(* Logix 5000 project; controller SmartVs_V02 1769-L33ERM rev 32.11; software revision 32.01; part 2 of 2 *)
(* tags used below, declared in another part *)
   UDP_Data : SKT_DATA_UDP;   // Holds all data sent and recieved by message instructions
   Enable_Socket : BOOL;   // Set by user to enable or disable socket
   ENABLED : BOOL;
   OPEN : BOOL;   // The Socket is Open
   READ : BOOL;   // New data in read buffer.
   WRITE : BOOL;   // Set bit to write data.
   ERROR : BOOL;   // Set if any message has an error.
   State : DINT;   // Current state
(* SKT_AOI_UDP, continued *)

ROUTINE Prescan   (* ladder *)
// Prescan
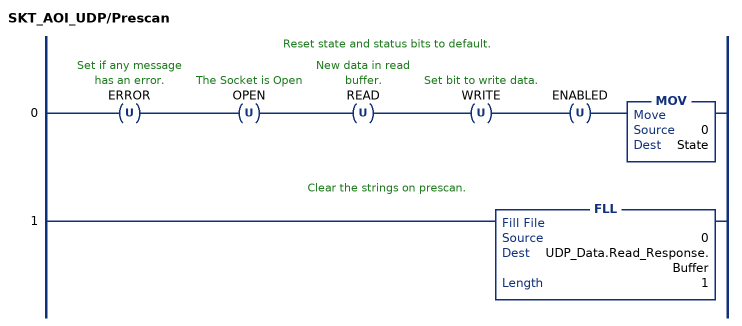
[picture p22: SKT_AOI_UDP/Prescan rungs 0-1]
   // Reset state and status bits to default.
   0: OTU(ERROR)OTU(OPEN)OTU(READ)OTU(WRITE)OTU(ENABLED)MOV(0,State);
   // Clear the strings on prescan.
   1: FLL(0,UDP_Data.Read_Response.Buffer,1);
END_ROUTINE
END_ADD_ON_INSTRUCTION

ADD_ON_INSTRUCTION SmartVS   (* revision 1.0 *)
VAR_INPUT
   i_xEnable : BOOL;
   i_xWrite : BOOL;
   i_xReset : BOOL;
   i_iJobData : INT;
END_VAR
VAR_OUTPUT
   o_xEnabled : BOOL; {access Read Only}
   o_xError : BOOL; {access Read Only}
END_VAR
VAR_IN_OUT
   o_sStringResult : STRING; {required}
END_VAR
VAR_OUTPUT
   o_iErrorCode : INT; {access Read Only}
END_VAR
VAR_INPUT
   i_iIPaddr1 : INT;
   i_iIPaddr2 : INT;
   i_iIPaddr3 : INT;
   i_iIPaddr4 : INT;
END_VAR
VAR_IN_OUT
   MSG_Client_Connect : MESSAGE; {required}
   DATA_Client : SKT_DATA_CLIENT; {required}
   MSG_Client_Create : MESSAGE; {required}
   MSG_Client_Delete : MESSAGE; {required}
   MSG_Client_Read : MESSAGE; {required}
   MSG_Client_Write : MESSAGE; {required}
   MSG_Delete_All : MESSAGE; {required}
END_VAR
VAR_OUTPUT
   o_diExtErrorCode : DINT; {access Read Only}
END_VAR
VAR
   Client_Buffer : STR_480;
   iErrorCode : INT; {access None}
   iErrorState : INT; {access None}
   Write_Data_Client : BOOL;
   Write_Data_Server : BOOL;
   Write_Data_UDP : BOOL;
   ifindDONE : INT; {access None}
   ifindFAIL : INT; {access None}
   iOldJobData : INT := -1; {access None}
   iOldIPaddr1 : INT := -1; {access None}
   sJobDone : STRING := 'Job DONE';
   sJobFailed : STRING := 'Job FAIL';
   sJobLoadString : STRING := 'job load ';
   String_1 : STRING;
   sRLString : STRING := '$0D$0A';
   String_3 : STRING;
   String_4 : STRING;
   xBitTrig : FBD_ONESHOT := (InputBit := 1);
   xDeleteMsg : BOOL;
   iOldIPaddr2 : INT := -1; {access None}
   iOldIPaddr3 : INT := -1; {access None}
   sJobData : STRING; {access None}
   diString_1Len : DINT; {access None}
   sDONE : STRING := 'DONE'; {access None}
   sFAIL : STRING := 'FAIL'; {access None}
   sResponseError : STRING := 'Response Error'; {access None}
   sErrorState : STRING := 'Error State'; {access None}
   sIPaddr1 : STRING; {access None}
   sIPaddr2 : STRING; {access None}
   sIPaddr3 : STRING; {access None}
   sIPaddr4 : STRING; {access None}
   sDot : STRING := '.'; {access None}
   sDotIPaddr4 : STRING; {access None}
   sDotIPaddr2 : STRING; {access None}
   sDotIPaddr3 : STRING; {access None}
   sIPaddrComplete : STRING; {access None}
   sPortNumber : STRING := '?port=23'; {access None}
   sEmpty : STRING; {access None}
   ReadTimer : FBD_TIMER; {access None}
   iOldIPaddr4 : INT := -1; {access None}
   iQuantity : INT; {access None}
   iStartCopy : INT; {access None}
   iState : INT; {access None}
   sLRRL : STRING := '$0A$0D$0D$0A'; {access None}
   iFailInfoEnd : DINT; {access None}
   sJobFailedInfo : STRING; {access None}
   sJobFailedCompleted : STRING; {access None}
   iExtErrorCode : DINT; {access None}
   TCP_Client : SKT_AOI_TCP_CLIENT; {access None}
   StringResetTimer : FBD_TIMER; {access None}
   sSmartVSanswer : STRING; {access None}
   String_5 : STRING; {access None}
   sSearchDONE : STRING; {access None}
   sSearchFAIL : STRING; {access None}
   ifindFAIL_1 : INT;
   SmartVS_DB : INT; {access None}
   sSpace : STRING := ' '; {access None}
   String_2 : STRING; {access None}
END_VAR

ROUTINE Logic   (* structured text *)
   
   //AOI used for TCP/IP communication with Datalogic SmartVS in order to perform "job change" opearation
   //Author: Lorenzo Draghetti
   
   
   //Delete all sockets at start and reset
   if S:FS OR xDeleteMsg then
   	MSG(MSG_Delete_All);
   	xDeleteMsg := 0;
   end_if;
   
   //Set time to wait before to read SmartVS' answer
    ReadTimer.PRE := 300; //300 ms
    TONR(ReadTimer);
   
   //Trigger of Write command
    xBitTrig.InputBit := i_xWrite;
    OSRI(xBitTrig);
   
   //Transfer SmartVS' answer to client buffer (which is not automatically emptied unlike DATA_Client.Read_Response.Buffer)
   if TCP_Client.READ then
   	TCP_Client.READ := 0;
   	COP (DATA_Client.Read_Response.Buffer, Client_Buffer, 1);
   end_if;
   
   //AOI for TCP/IP communication
   SKT_AOI_TCP_CLIENT (TCP_Client, DATA_Client, MSG_Client_Create, MSG_Client_Connect, MSG_Client_Read, MSG_Client_Write, MSG_Client_Delete);
   
   
   
   
   //State machine:  0   - Start Socket Creation
   //				  5   - Socket Creation in progress
   //				  10  - Start Socket Connection
   //				  15  - Socket Connection in progress
   //  			  20  - Start Writing
   //				  25  - Writing in progress
   //				  30  - Reading
   //    			  40  - Start Deleting
   //                45  - Deleting in progress
   //    			  99  - Error State
   //				  100 - Reset State
   
   
   
   
   
   
   case iState of
   
   	0:			//Start Socket Creation
   
   
   
   	   	if i_xEnable then							//Update IP address (only if it has changed)
   			if i_iIPaddr1 <> iOldIPaddr1 then
   				iOldIPaddr1 := i_iIPaddr1;
   	   			DTOS(i_iIPaddr1, sIPaddr1);
   			end_if;
   
   			if i_iIPaddr2 <> iOldIPaddr2 then
   				iOldIPaddr2 := i_iIPaddr2;
   	   			DTOS(i_iIPaddr2, sIPaddr2);
   	   			CONCAT(sDot, sIPaddr2, sDotIPaddr2);
   			end_if;
   
   			if i_iIPaddr3 <> iOldIPaddr3 then
   				iOldIPaddr3 := i_iIPaddr3;
   	   			DTOS(i_iIPaddr3, sIPaddr3);
   	   			CONCAT(sDot, sIPaddr3, sDotIPaddr3);
   			end_if;
   
   			if i_iIPaddr4 <> iOldIPaddr4 then
   				iOldIPaddr4 := i_iIPaddr4;
   	   			DTOS(i_iIPaddr4, sIPaddr4);
   	   			CONCAT(sDot, sIPaddr4, sDotIPaddr4);
   	   		end_if;
   
   		    COP(sEmpty, DATA_Client.Connect_Source.DestAddr, 1);
   
   		   	INSERT(DATA_Client.Connect_Source.DestAddr, sIPaddr1, 1, DATA_Client.Connect_Source.DestAddr);
   	   		CONCAT(DATA_Client.Connect_Source.DestAddr, sDotIPaddr2, DATA_Client.Connect_Source.DestAddr);
   	   		CONCAT(DATA_Client.Connect_Source.DestAddr, sDotIPaddr3, DATA_Client.Connect_Source.DestAddr);
   	   		CONCAT(DATA_Client.Connect_Source.DestAddr, sDotIPaddr4, DATA_Client.Connect_Source.DestAddr);
   	   		CONCAT(DATA_Client.Connect_Source.DestAddr, sPortNumber, DATA_Client.Connect_Source.DestAddr);    //create IP address and port string (must be in the format "xxx.xxx.xxx.xxx?port=x")
   	   	end_if;
   
   	   	TCP_Client.Enable_Socket := i_xEnable;   //enable to create and connect socket
   
   		IF MSG_Client_Create.ST and i_xEnable then
   
   			iState := 5;
   
   	   elsif MSG_Client_Create.ER and i_xEnable then
   
   			iErrorCode := MSG_Client_Create.ERR;
   			iExtErrorCode := MSG_Client_Create.EXERR;
   			iErrorState := 0;
   	        iState := 99;
   
   	   end_if;
   
   
   
   
   	5:			//Socket Creation in progress
   
   
   		if MSG_Client_Create.DN AND i_xEnable then
   
   			iState := 10;
   
   	   	elsif MSG_Client_Create.ER AND i_xEnable then
   
   			iErrorCode := MSG_Client_Create.ERR;
   			iExtErrorCode := MSG_Client_Create.EXERR;
   			iErrorState := 5;
   	        iState := 99;
   
   	   	end_if;
   
   
   
   	10:			//Start Socket Connection
   
   
          	if MSG_Client_Connect.ST AND i_xEnable then
   
   			iState := 15;
   
   	  	elsif MSG_Client_Connect.ER AND i_xEnable then
   
   			iErrorCode := MSG_Client_Connect.ERR;
   			iExtErrorCode := MSG_Client_Connect.EXERR;
   			iErrorState := 10;
   			iState := 99;
   
   		elsif not i_xEnable then   //if i_xEnable is FALSE --> Disconnect/Delete Socket
   			iState := 40;
   	   	end_if;
   
   
   	15:			//Socket Connection in progress
   
   		if MSG_Client_Connect.DN AND i_xEnable then
   	    	o_xEnabled := 1;
   			iState := 20;
   
   	  	elsif MSG_Client_Connect.ER AND i_xEnable then
   
   			iErrorCode := MSG_Client_Connect.ERR;
   			iExtErrorCode := MSG_Client_Connect.EXERR;
   			iErrorState := 15;
   			iState := 99;
   
   		elsif not i_xEnable then  //if i_xEnable is FALSE --> Disconnect/Delete Socket
   			iState := 40;
   
   	   	end_if;
   
   
   
   
   
   	20:			//Start writing
   
   
   		if xBitTrig.OutputBit then
   
   
   			//create the string to send to SmartVS (and put in the Write Buffer)
   			DTOS(i_iJobData,sJobData);
   			INSERT(sJobLoadString,sJobData,10,String_1);
   			diString_1Len:=String_1.LEN + 1;
       		INSERT(String_1, sRLString, diString_1Len, String_3);
   			COP(String_3, DATA_Client.Write_Source.Buffer, 1);
   			TCP_Client.WRITE := 1;
   
   			COP(sEmpty, o_sStringResult, 1);
   
   
   		end_if;
   
   
   		if MSG_Client_Write.ST AND i_xEnable then
   
   			TCP_Client.WRITE := 0;
   			iState := 25;
   
   		elsif MSG_Client_Write.ER AND i_xEnable then
   
   			iErrorCode := MSG_Client_Write.ERR;
   			iExtErrorCode := MSG_Client_Write.EXERR;
   			iErrorState := 20;
   			iState := 99;
   
   		elsif MSG_Client_Read.ER AND i_xEnable then   //this condition is for detecting a disconnection of SmartVS while we are in "Start Writing" state --->
   													  // ---> it's related to the behaviour of SKT_AOI_TCP_CLIENT (it continuosly try to read even without a write command)
   
   			iErrorCode := MSG_Client_Read.ERR;
   			iExtErrorCode := MSG_Client_Read.EXERR;
   			iErrorState := 20;
   			iState := 99;
   
   		elsif NOT i_xEnable then  //if i_xEnable is FALSE --> Disconnect/Delete Socket
   
   			iState := 40;
   
   		end_if;
   
   
   	25:			//Writing in progress
   
   
   		if MSG_Client_Write.DN AND i_xEnable then
   
   			TCP_Client.WRITE := 0;
   			iState := 30;
   
   		elsif MSG_Client_Write.ER AND i_xEnable then
   
   			iErrorCode := MSG_Client_Write.ERR;
   			iExtErrorCode := MSG_Client_Write.EXERR;
   			iErrorState := 25;
   			iState := 99;
   
   		elsif NOT i_xEnable then  //if i_xEnable is FALSE --> Disconnect/Delete Socket
   
   			iState := 40;
   
   		end_if;
   
   
   
   	30:			//Reading
   
   
   		ReadTimer.TimerEnable := 1;
   		if MSG_Client_Read.DN AND i_xEnable then
   
   			if ReadTimer.DN then   //Wait timer for being sure to read the whole string
   
   				ReadTimer.TimerEnable := 0;
   				CONCAT(sJobData,sRLString,String_4);
   				CONCAT(String_4, sDONE, sSearchDONE);
   				CONCAT(String_4,sFAIL,sSearchFAIL);
   
   
   				FIND (Client_Buffer, sSearchDONE, 1, ifindDONE);    //search in Client_Buffer for 'x$r$lDONE'
   				FIND (Client_Buffer, sSearchFAIL, 1, ifindFAIL);	//search in Client_Buffer for 'x$r$lFAIL'
   
   				if ifindDONE > 0 then  //job loaded correctly
   
   					CONCAT(sJobData, sSpace, String_2);
   					INSERT(sJobDone, String_2, 5, String_2);
   					COP(String_2, o_sStringResult, 1);
   					iState := 20;
   
   				elsif ifindFAIL > 0 then  //job not loaded ---> fail info are provided in output (o_sStringResult)
   
   					FIND(Client_Buffer, sFAIL, 1, ifindFAIL_1);
   					FIND(Client_Buffer, sLRRL, ifindFAIL_1, iFailInfoEnd);
   					iQuantity := iFailInfoEnd-(ifindFAIL_1+4);
   					iStartCopy := ifindFAIL_1+4;
   					MID(Client_Buffer, iQuantity, iStartCopy, sJobFailedInfo);
   					CONCAT(sJobData, sSpace, String_2);
   					INSERT(sJobFailed, String_2, 5, String_2);
   					CONCAT(String_2, sJobFailedInfo, sJobFailedCompleted);
   					COP(sJobFailedCompleted, o_sStringResult, 1);
   					iState := 20;
   
   				else  //PLC hasn't received neither DONE neither FAIL ---> error in SmartVS' answer
   
   					COP(sResponseError, o_sStringResult, 1);
   					iErrorCode := 16#0017;
   					iErrorState := 30;
   					iState := 99;
   
   				end_if;
   
   				COP(Client_Buffer, sSmartVSanswer, 1);
   				COP(sEmpty, Client_Buffer, 1);
   
   			end_if;
   
   		elsif MSG_Client_Read.ER AND i_xEnable then
   
   			iErrorCode := MSG_Client_Read.ERR;
   			iExtErrorCode := MSG_Client_Read.EXERR;
   			iErrorState := 30;
   			iState := 99;
   
   		elsif not i_xEnable then  //if i_xEnable is FALSE --> Disconnect/Delete
   
   			iState := 40;
   
   		end_if;
   
   
   
   
   	40:			//Start Deleting Socket
   
   		TCP_Client.Enable_Socket := 0;
   
   		if MSG_Client_Delete.ST then
   
   			iState := 45;
   
   		elsif MSG_Client_Delete.ER then
   
   			iErrorCode := MSG_Client_Delete.ERR;
   			iExtErrorCode := MSG_Client_Delete.EXERR;
   			iErrorState := 40;
   			iState := 99;
   
   		end_if;
   
   
   	45:			//Deleting Socket in progress
   
   		if MSG_Client_Delete.DN then
   
   			o_xEnabled := 0;
   			COP(sEmpty, o_sStringResult, 1);
   			COP(sEmpty, Client_Buffer, 1);
   			iState := 0;
   
   		elsif MSG_Client_Delete.ER then
   
   			iErrorCode := MSG_Client_Delete.ERR;
   			iExtErrorCode := MSG_Client_Delete.EXERR;
   			iErrorState := 45;
   			iState := 99;
   
   		end_if;
   
   
   
   
   	99:			//Error State
   
   
   		o_xError := 1;
   		o_iErrorCode := iErrorCode;
   		o_diExtErrorCode := iExtErrorCode;
   		COP(sErrorState, o_sStringResult, 1);
   
   		if i_xReset then
   
   			if iErrorCode = 16#0017 then    /// 16#0017 ---> error in SmartVS' answer
   				o_iErrorCode := 0;
   				o_diExtErrorCode := 0;
   				o_xError := 0;
   				COP(sEmpty, o_sStringResult, 1);
   				COP(sEmpty, Client_Buffer, 1);
   				iState := 20;
   
   
   			else
   
   				iState := 100;
   
   			end_if;
   
   		end_if;
   
   
   	100:		//Reset State
   
   
   
   		TCP_Client.Enable_Socket := 0;
   		TCP_Client.WRITE := 0;
   		xDeleteMsg := 1;
   		o_xEnabled := 0;
   		o_iErrorCode :=0;
   		o_diExtErrorCode := 0;
   		o_xError :=0;
   		COP(sEmpty, o_sStringResult, 1);
   		COP(sEmpty, Client_Buffer, 1);
   
   		iState := 0;
   
   
   end_case;
   
   
   
   
   
END_ROUTINE
END_ADD_ON_INSTRUCTION

VAR_GLOBAL   (* controller tags *)
   client : SKT_DATA_CLIENT := (Timeout := 2000, Create_Source.Type := 1, Create_Source.Addr.Family := 2, Create_Source.Addr.Port := 2000, Instance := 23681, Connect_Source.Timeout := 2000, Read_Source.Timeout := 2000, Read_Source.BufLen := 480, Write_Source.Timeout := 2000, Write_Source.ToAddr.Family := 2, Write_SizeSent := 20);
   connect : MESSAGE;
        MessageParameters(ServiceCode := 16#004c, LocalElement := client.Connect_Source, ...)
   create : MESSAGE;
        MessageParameters(ServiceCode := 16#004b, LocalElement := client.Create_Source, DestinationTag := client.Instance, ...)
   delete : MESSAGE;
        MessageParameters(ServiceCode := 16#004f, ...)
   deleteall : MESSAGE;
        MessageParameters(ServiceCode := 16#0051, ...)
   diFeedbacklenght : DINT := 11;
   diProva : DINT := 16;
   iIndex : DINT := 15;
   iIndex_2 : INT := 8;
   iJ : DINT := 16;
   iprova : INT := 12;
   readmsg : MESSAGE;
        MessageParameters(ServiceCode := 16#004d, LocalElement := client.Read_Source, DestinationTag := client.Read_Response, ...)
   sJobDone : STRING := 'Job Done';
   sJobFailed : STRING := 'Job Fail';
   sJobLoadString : STRING := 'job load ';
   SKT_AOI_Client : SKT_AOI_TCP_CLIENT := (Enable_Socket := 1, ENABLED := 1, OPEN := 1);
   SKT_AOI_Server : SKT_AOI_TCP_SERVER;
   SKT_AOI_UDP : SKT_AOI_UDP;
   SKT_DATA_Client : SKT_DATA_CLIENT := (Timeout := 2000, Create_Source.Type := 1, Create_Source.Addr.Family := 2, Create_Source.Addr.Port := 2000, Instance := 23681, Connect_Source.Timeout := 2000, Read_Source.Timeout := 2000, Read_Source.BufLen := 480, Write_Source.Timeout := 2000, Write_Source.ToAddr.Family := 2, Write_SizeSent := 20);
   SKT_DATA_Server : SKT_DATA_SERVER := (Timeout := 2000, Create_Source.Type := 1, Create_Source.Addr.Family := 2, Create_Source.Addr.Port := 45, Accept_Socket_Instance := 20801, Accept_Timeout := 2000, Accept_Response.Instance := 24735, Accept_Response.Addr.Family := 2, Accept_Response.Addr.Port := -11587, Accept_Response.Addr.Addr[0] := 28, Accept_Response.Addr.Addr[1] := 48, Accept_Response.Addr.Addr[2] := 16, Accept_Response.Addr.Addr[3] := 10, Read_Source.Timeout := 2000, Read_Source.BufLen := 480, Write_Source.Timeout := 2000, Write_Source.ToAddr.Family := 2, Write_Source.Buffer := 'ma chi ti caga', Write_SizeSent := 14);
   SKT_DATA_UDP : SKT_DATA_UDP := (Timeout := 2000, Create_Source.Type := 2, Create_Source.Addr.Family := 2, Create_Source.Addr.Port := 10000, Connect_Source.Timeout := 2000, Connect_Source.DestAddr := '192.168.1.200?port=10000', Read_Source.Timeout := 2000, Read_Source.BufLen := 480, Write_Source.Timeout := 2000, Write_Source.ToAddr.Family := 2, Write_Source.Buffer := 'Some sample text', Instance := 29590, Read_Response.FromAddr.Family := 2, Read_Response.FromAddr.Port := 10000, Read_Response.FromAddr.Addr[0] := -56, Read_Response.FromAddr.Addr[1] := 1, Read_Response.FromAddr.Addr[2] := -88, Read_Response.FromAddr.Addr[3] := -64, Write_SizeSent := 16);
        .Create_Source.Addr.Addr   // Not use for create
   SKT_MSG_Client_Connect : MESSAGE;
        MessageParameters(ServiceCode := 16#004c, LocalElement := SKT_DATA_Client.Connect_Source, ...)
   SKT_MSG_Client_Create : MESSAGE;
        MessageParameters(ServiceCode := 16#004b, LocalElement := SKT_DATA_Client.Create_Source, DestinationTag := SKT_DATA_Client.Instance, ...)
   SKT_MSG_Client_Delete : MESSAGE;
        MessageParameters(ServiceCode := 16#004f, ...)
   SKT_MSG_Client_Read : MESSAGE;
        MessageParameters(ServiceCode := 16#004d, LocalElement := SKT_DATA_Client.Read_Source, DestinationTag := SKT_DATA_Client.Read_Response, ...)
   SKT_MSG_Client_Write : MESSAGE;
        MessageParameters(ServiceCode := 16#004e, LocalElement := SKT_DATA_Client.Write_Source, DestinationTag := SKT_DATA_Client.Write_SizeSent, ...)
   SKT_MSG_Delete_All : MESSAGE;
        MessageParameters(ServiceCode := 16#0051, ...)
   SKT_MSG_Server_Accept : MESSAGE;
        MessageParameters(ServiceCode := 16#0050, LocalElement := SKT_DATA_Server.Accept_Timeout, DestinationTag := SKT_DATA_Server.Accept_Response, ...)
   SKT_MSG_Server_Create : MESSAGE;
        MessageParameters(ServiceCode := 16#004b, LocalElement := SKT_DATA_Server.Create_Source, DestinationTag := SKT_DATA_Server.Accept_Socket_Instance, ...)
   SKT_MSG_Server_Delete : MESSAGE;
        MessageParameters(ServiceCode := 16#004f, ...)
   SKT_MSG_Server_Read : MESSAGE;
        MessageParameters(ServiceCode := 16#004d, LocalElement := SKT_DATA_Server.Read_Source, DestinationTag := SKT_DATA_Server.Read_Response, ...)
   SKT_MSG_Server_Write : MESSAGE;
        MessageParameters(ServiceCode := 16#004e, LocalElement := SKT_DATA_Server.Write_Source, DestinationTag := SKT_DATA_Server.Write_SizeSent, ...)
   SKT_MSG_UDP_Connect : MESSAGE;
        MessageParameters(ServiceCode := 16#004c, LocalElement := SKT_DATA_UDP.Connect_Source, ...)
   SKT_MSG_UDP_Create : MESSAGE;
        MessageParameters(ServiceCode := 16#004b, LocalElement := SKT_DATA_UDP.Create_Source, DestinationTag := SKT_DATA_UDP.Instance, ...)
   SKT_MSG_UDP_Delete : MESSAGE;
        MessageParameters(ServiceCode := 16#004f, ...)
   SKT_MSG_UDP_Read : MESSAGE;
        MessageParameters(ServiceCode := 16#004d, LocalElement := SKT_DATA_UDP.Read_Source, DestinationTag := SKT_DATA_UDP.Read_Response, ...)
   SKT_MSG_UDP_Write : MESSAGE;
        MessageParameters(ServiceCode := 16#004e, LocalElement := SKT_DATA_UDP.Write_Source, DestinationTag := SKT_DATA_UDP.Write_SizeSent, ...)
   SmartVs : UDT_SmartVs := (i_xEnable := 1, i_sJobData := '7', o_xEnabled := 1, iState := 8, i_iJobData := 7, sFeedback := ' DONE  ', diStringlen := 11);
   String_1 : STRING := 'job load 7';
   String_2 : STRING := '$0D$0A';
   String_3 : STRING := 'job load 7$0D$0A';
   String_4 : STRING := 'job load 7 DONE  $0D$0A';
   writemsg : MESSAGE;
        MessageParameters(ServiceCode := 16#004e, LocalElement := client.Write_Source, DestinationTag := client.Write_SizeSent, ...)
   xBitTrig : FBD_ONESHOT[10] := ([0].InputBit := 1);
   xDeleteMsg : BOOL;
   xDone : DINT;
   xEnable_FB : BOOL := 1;
   xFail : BOOL := 1;
   xWrite_FB : BOOL := 1;
END_VAR

PROGRAM MainProgram   (* main routine Main *)
VAR
   AOI_CLIENT2 : SKT_AOI_TCP_CLIENT;
   Client_Buffer : STR_480 := 'Smart-VS>';
   Enable_Client : BOOL := 1;
   Enable_Server : BOOL;
   Enable_UDP : BOOL;
   FALSE : BOOL; {constant}
   iOldJobData : INT := 7;
   SKT_Toggle : DINT := 1056;
        .0   // Toggle to delete all sockets
   SmartVS_DB : SmartVS;
   stringResult : STRING;
   UDP_Buffer : STR_480 := 'Some sample text';
   Write_Data_Client : BOOL;
   Write_Data_Server : BOOL;
   Write_Data_UDP : BOOL;
   xIncState : BOOL;
END_VAR

ROUTINE Main   (* ladder *)
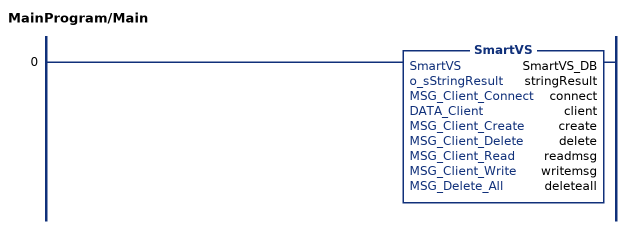
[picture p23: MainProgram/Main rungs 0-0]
   0: SmartVS(SmartVS_DB,stringResult,connect,client,create,delete,readmsg,writemsg,deleteall);
END_ROUTINE

ROUTINE SmartVS   (* structured text *)
// FB SmartVs Datalogic
   
   
   OSRI(xBitTrig[1]);
   xBitTrig[1].InputBit :=SmartVs.i_xWrite;
   Enable_Client:= SmartVs.i_xEnable;
   
   
   if SmartVs.iq_xResetFB      //Reset all and start from zero
   then
   Enable_Client   :=0;
   SKT_Toggle.0         :=1;
   SmartVs.o_iErrorCode :=0;
   SmartVs.iState       :=0;
   SmartVs.o_xError     :=0;
   SmartVs.iq_xResetFB  :=0;
   end_if;
   
   if  SmartVs.i_iJobData <> iOldJobData
   then
   	if SmartVs.i_iJobData<0 or SmartVs.i_iJobData>31
       then SmartVs.o_xError:=1;
       else
   	DTOS(SmartVs.i_iJobData, SmartVs.i_sJobData);
   	iOldJobData:=SmartVs.i_iJobData;
   	iIndex:=0;
   	INSERT(sJobLoadString,SmartVs.i_sJobData,10,String_1);
   	SmartVs.diStringlen:=String_1.LEN+1;
       INSERT(String_1,String_2,	SmartVs.diStringlen,String_3);
   	    while iIndex<15 do
   		   SKT_DATA_Client.Write_Source.Buffer.DATA[iIndex]:=String_3.DATA[iIndex];
   		   iIndex:=iIndex+1;
   
   
   	    end_while;
   	SmartVs.o_xError:=0;
   	end_if;
   end_if;
   
   if xIncState
   then
   SmartVs.iState:=SmartVs.iState+1 ;
   xIncState:=0;
   end_if;
   
   
   case SmartVs.iState of
   
   	0:
   	   if  SmartVs.i_xEnable and not SKT_MSG_Client_Create.ER and not SKT_MSG_Client_Connect.ER then
   
   			xIncState    :=1;
   
   	   elsif SmartVs.i_xEnable and SKT_MSG_Client_Create.ERR<>0 then
   
   			SmartVs.o_iErrorCode:=SKT_MSG_Client_Create.ERR;
   	      	SmartVs.o_xError:=1;                                                   //Stato da cui si può uscire solo se si preme un Reset
   
   	   elsif SmartVs.i_xEnable and SKT_MSG_Client_Connect.ERR<>0 then
   
   			SmartVs.o_iErrorCode:=SKT_MSG_Client_Connect.ERR;
   	        SmartVs.o_xError:=1;
   
   	   end_if;
   
   
   	1:
   
          if SKT_MSG_Client_Create.DN and SKT_MSG_Client_Connect.DN then
   
       		SmartVs.o_xEnabled     :=1;                                                    //Socket created and connected
   			xIncState              :=1;
   
   	   else
   			SmartVs.o_xEnabled :=0;
   			SmartVs.iState :=0;
   
   	   end_if;
   	2:
   
   	   if   xBitTrig[1].OutputBit and not SKT_MSG_Client_Create.ER and not SKT_MSG_Client_Connect.ER
   	   then Write_Data_Client  :=1;
   		     xIncState         :=1;
   	   elsif SKT_MSG_Client_Create.ERR<>0
   	   then  SmartVs.o_iErrorCode:=SKT_MSG_Client_Create.ERR;
   	         SmartVs.o_xError:=1;
   			 SmartVs.iState:=-1;
   
   	   elsif SKT_MSG_Client_Connect.ERR<>0
   	   then  SmartVs.o_iErrorCode:=SKT_MSG_Client_Connect.ERR;
   	         SmartVs.o_xError:=1;
   			 SmartVs.iState  :=-1;
   	   end_if;
   	3:
   		if  SKT_MSG_Client_Write.DN
   		then xIncState           :=1;
   		elsif SKT_MSG_Client_Write.ERR<>0
   		then  SmartVs.o_iErrorCode:=SKT_MSG_Client_Write.ERR;
   			  SmartVs.o_xError   :=1;
   			  SmartVs.iState     :=-1;
   
   		end_if;
   
   	4:
   
   	   diFeedbacklenght:=String_3.LEN-1;
   	   INSERT(String_3,SmartVs.sFeedback,diFeedbacklenght,String_4);
   	   	xIncState:=1;
       5:
   		 iJ:=0;
   		while iJ<diProva do //String_4.LEN do
   		  if SKT_DATA_Client.Read_Response.Buffer.DATA[iJ]<>String_4.DATA[iJ]
   		  then xFail:=1;
   		  else
   			   xFail:=0;
   		  end_if;
   		  iJ:=iJ+1;
   		end_while;
   		xIncState:=1;
   	6:
   		if  SKT_MSG_Client_Read.DN
   		then
   		     if not xFail
   	         then xDone:=1;
   			 else
   			      xDone:=0;
   			end_if;
   		xIncState:=1;
   		elsif SKT_MSG_Client_Read.ERR<>0
   		then  SmartVs.o_iErrorCode:=SKT_MSG_Client_Read.ERR;
   			  SmartVs.o_xError   :=1;
   			  SmartVs.iState     :=-1;
   
   		end_if;
   
      7:
   	    iIndex_2:=0;
   		while iIndex_2<sJobDone.LEN  do
   		if xDone=1
   		then	SmartVs.o_sJobResult.DATA[iIndex_2]:= sJobDone.DATA[iIndex_2];
   		else
   	         	SmartVs.o_sJobResult.DATA[iIndex_2]:= sJobFailed.DATA[iIndex_2];
   		end_if;
   		iIndex_2:=iIndex_2+1;
   		end_while;
   		xIncState:=1;
      8:
   		SmartVs.iState :=0;
   
   
   
   
   
   
   
   
   
   end_case;
   
END_ROUTINE

ROUTINE TCP_CLIENT   (* ladder *)
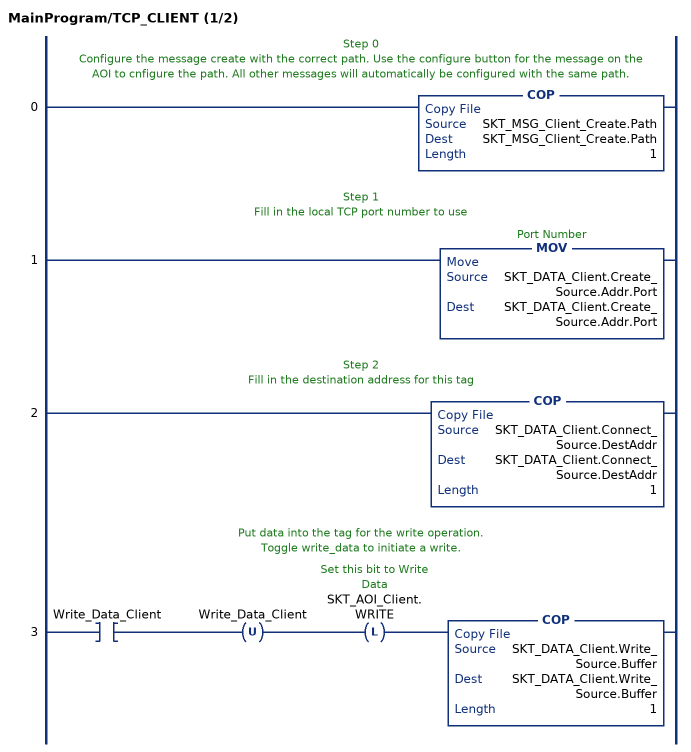
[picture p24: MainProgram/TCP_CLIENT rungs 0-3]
   // Step 0
   // Configure the message create with the correct path. Use the configure button for the message on the AOI to cnfigure the path. All other messages will automatically be configured with the same path.
   0: COP(SKT_MSG_Client_Create.Path,SKT_MSG_Client_Create.Path,1);
   // Step 1
   // Fill in the local TCP port number to use
   1: MOV(SKT_DATA_Client.Create_Source.Addr.Port,SKT_DATA_Client.Create_Source.Addr.Port);
   // Step 2
   // Fill in the destination address for this tag
   2: COP(SKT_DATA_Client.Connect_Source.DestAddr,SKT_DATA_Client.Connect_Source.DestAddr,1);
   // Put data into the tag for the write operation.
   // Toggle write_data to initiate a write.
   3: XIC(Write_Data_Client)OTU(Write_Data_Client)OTL(SKT_AOI_Client.WRITE)COP(SKT_DATA_Client.Write_Source.Buffer,SKT_DATA_Client.Write_Source.Buffer,1);
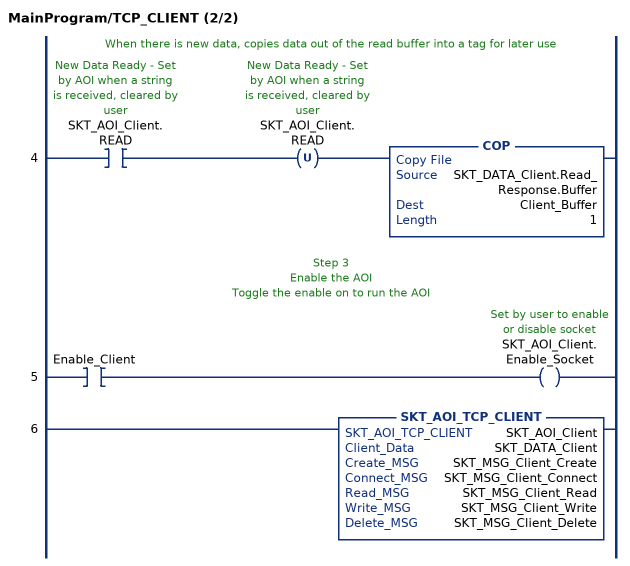
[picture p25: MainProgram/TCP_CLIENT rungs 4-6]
   // When there is new data, copies data out of the read buffer into a tag for later use
   4: XIC(SKT_AOI_Client.READ)OTU(SKT_AOI_Client.READ)COP(SKT_DATA_Client.Read_Response.Buffer,Client_Buffer,1);
   // Step 3
   // Enable the AOI
   // Toggle the enable on to run the AOI
   5: XIC(Enable_Client)OTE(SKT_AOI_Client.Enable_Socket);
   6: SKT_AOI_TCP_CLIENT(SKT_AOI_Client,SKT_DATA_Client,SKT_MSG_Client_Create,SKT_MSG_Client_Connect,SKT_MSG_Client_Read,SKT_MSG_Client_Write,SKT_MSG_Client_Delete);
END_ROUTINE
END_PROGRAM
